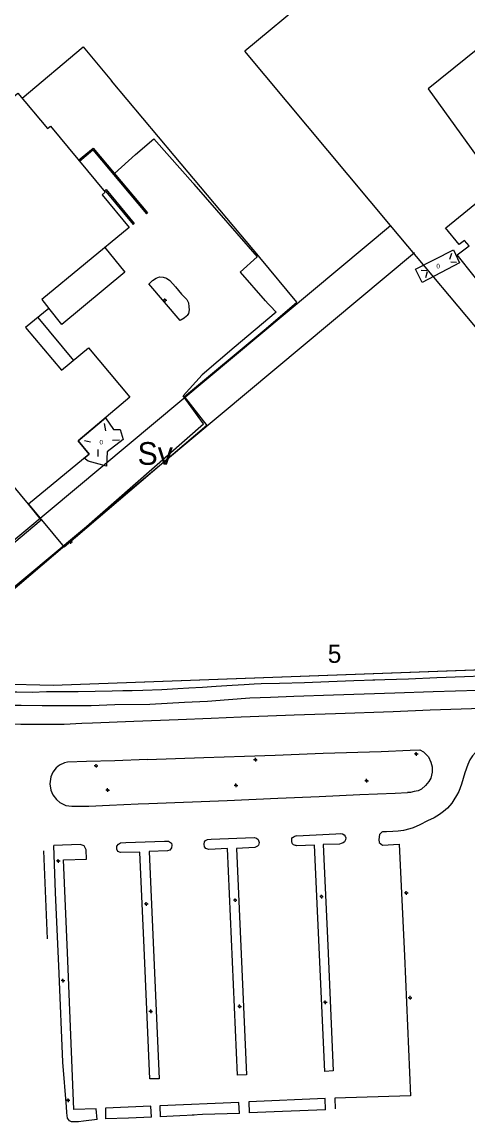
# Model space of a CAD drawing. Extents: x 1517229 to 1518128, y 6494851 to 6495271.
# Drawn here: x 1517777.6 to 1517875.8, y 6494851.1 to 6495093.3 of the extents above; entities that cross this region are included whole.
import ezdxf

# ---------------------------------------------------------------- set-up
doc = ezdxf.new("R2010")
doc.units = 0
doc.layers.add('Karta', color=7, linetype='Continuous')

msp = doc.modelspace()

# ---------------------------------------------------------------- linework, layer by layer
at = {"layer": 'Karta'}
for p, q in [((1517881.78, 6495132.98), (1517826.66, 6495086.92)), ((1517858.73, 6495048.55), (1517826.66, 6495086.92)), ((1517811.14, 6495063.95), (1517797.36, 6495080.37)), ((1517830.07, 6495041.4), (1517811.14, 6495063.95)), ((1517805.03, 6495051.11), (1517805.25, 6495051.3)), ((1517746.18, 6494954.49), (1517858.73, 6495048.55)), ((1517802.11, 6495048.74), (1517802.35, 6495048.94)), ((1517932.72, 6494960.01), (1517858.73, 6495048.55)), ((1517864, 6495042.53), (1517758.73, 6494954.55)), ((1517872.16, 6495042.37), (1517871.74, 6495041.05)), ((1517865.51, 6495038.71), (1517866.77, 6495038.65)), ((1517866.83, 6495038.29), (1517866.41, 6495036.97)), ((1517872.04, 6495040.51), (1517873.3, 6495040.45)), ((1517808.88, 6495032.09), (1517808.68, 6495032.09)), ((1517809.08, 6495032.29), (1517809.08, 6495032.49)), ((1517809.08, 6495031.89), (1517809.08, 6495031.69)), ((1517809.28, 6495032.09), (1517809.48, 6495032.09)), ((1517781.09, 6495028.24), (1517788.93, 6495018.83)), ((1517813.36, 6495010.85), (1517831.36, 6495025.87)), ((1517818.36, 6495004.5), (1517813.36, 6495010.85)), ((1517786.88, 6494977.74), (1517818.33, 6495004.54)), ((1517795.73, 6495004.9), (1517796.04, 6495003.32)), ((1517791.42, 6495001.18), (1517792.68, 6495000.9)), ((1517799.06, 6495001.29), (1517797.55, 6495001.22)), ((1517794.4, 6494997.68), (1517794.36, 6494999.18)), ((1517779.06, 6494987.16), (1517786.89, 6494977.73)), ((1517788.13, 6494978.85), (1517787.93, 6494978.85)), ((1517788.33, 6494979.05), (1517788.33, 6494979.25)), ((1517788.33, 6494978.65), (1517788.33, 6494978.45)), ((1517788.53, 6494978.85), (1517788.73, 6494978.85)), ((1517784.48, 6494947.28), (1517907.3, 6494951.79)), ((1517772.62, 6494947.63), (1517784.48, 6494947.28)), ((1517864.21, 6494932.17), (1517864.01, 6494932.17)), ((1517864.41, 6494932.37), (1517864.41, 6494932.57)), ((1517864.41, 6494931.97), (1517864.41, 6494931.77)), ((1517864.61, 6494932.17), (1517864.81, 6494932.17)), ((1517793.74, 6494929.55), (1517793.54, 6494929.55)), ((1517793.94, 6494929.75), (1517793.94, 6494929.95)), ((1517793.94, 6494929.35), (1517793.94, 6494929.15)), ((1517794.14, 6494929.55), (1517794.34, 6494929.55)), ((1517828.8, 6494930.9), (1517828.6, 6494930.9)), ((1517829, 6494931.1), (1517829, 6494931.3)), ((1517829, 6494930.7), (1517829, 6494930.5)), ((1517829.2, 6494930.9), (1517829.4, 6494930.9)), ((1517796.46, 6494924.42), (1517796.46, 6494924.62)), ((1517824.53, 6494925.25), (1517824.33, 6494925.25)), ((1517824.73, 6494925.45), (1517824.73, 6494925.65)), ((1517824.73, 6494925.05), (1517824.73, 6494924.85)), ((1517824.93, 6494925.25), (1517825.13, 6494925.25)), ((1517853.27, 6494926.27), (1517853.07, 6494926.27)), ((1517853.47, 6494926.47), (1517853.47, 6494926.67)), ((1517853.47, 6494926.07), (1517853.47, 6494925.87)), ((1517853.67, 6494926.27), (1517853.87, 6494926.27)), ((1517796.26, 6494924.22), (1517796.06, 6494924.22)), ((1517796.46, 6494924.02), (1517796.46, 6494923.82)), ((1517796.66, 6494924.22), (1517796.86, 6494924.22)), ((1517783.25, 6494891.47), (1517782.43, 6494910.86)), ((1517785.4, 6494908.6), (1517785.2, 6494908.6)), ((1517785.6, 6494908.8), (1517785.6, 6494909)), ((1517785.6, 6494908.4), (1517785.6, 6494908.2)), ((1517785.8, 6494908.6), (1517786, 6494908.6)), ((1517824.55, 6494900.17), (1517824.55, 6494900.37)), ((1517843.35, 6494900.77), (1517843.15, 6494900.77)), ((1517843.55, 6494900.97), (1517843.55, 6494901.17)), ((1517843.55, 6494900.57), (1517843.55, 6494900.37)), ((1517843.75, 6494900.77), (1517843.95, 6494900.77)), ((1517862.01, 6494901.57), (1517861.81, 6494901.57)), ((1517862.21, 6494901.77), (1517862.21, 6494901.97)), ((1517862.21, 6494901.37), (1517862.21, 6494901.17)), ((1517862.41, 6494901.57), (1517862.61, 6494901.57)), ((1517804.78, 6494899.15), (1517804.58, 6494899.15)), ((1517804.98, 6494899.35), (1517804.98, 6494899.55)), ((1517804.98, 6494898.95), (1517804.98, 6494898.75)), ((1517805.18, 6494899.15), (1517805.38, 6494899.15)), ((1517824.35, 6494899.97), (1517824.15, 6494899.97)), ((1517824.55, 6494899.77), (1517824.55, 6494899.57)), ((1517824.75, 6494899.97), (1517824.95, 6494899.97)), ((1517786.45, 6494882.25), (1517786.25, 6494882.25)), ((1517786.65, 6494882.45), (1517786.65, 6494882.65)), ((1517786.65, 6494882.05), (1517786.65, 6494881.85)), ((1517786.85, 6494882.25), (1517787.05, 6494882.25)), ((1517862.85, 6494878.48), (1517862.65, 6494878.48)), ((1517863.05, 6494878.68), (1517863.05, 6494878.88)), ((1517863.05, 6494878.28), (1517863.05, 6494878.08)), ((1517863.25, 6494878.48), (1517863.45, 6494878.48)), ((1517805.97, 6494875.68), (1517805.97, 6494875.88)), ((1517825.33, 6494876.57), (1517825.13, 6494876.57)), ((1517825.53, 6494876.77), (1517825.53, 6494876.97)), ((1517825.53, 6494876.37), (1517825.53, 6494876.17)), ((1517825.73, 6494876.57), (1517825.93, 6494876.57)), ((1517844.18, 6494877.48), (1517843.98, 6494877.48)), ((1517844.38, 6494877.68), (1517844.38, 6494877.88)), ((1517844.38, 6494877.28), (1517844.38, 6494877.08)), ((1517844.58, 6494877.48), (1517844.78, 6494877.48)), ((1517805.77, 6494875.48), (1517805.57, 6494875.48)), ((1517805.97, 6494875.28), (1517805.97, 6494875.08)), ((1517806.17, 6494875.48), (1517806.37, 6494875.48)), ((1517787.59, 6494855.91), (1517787.39, 6494855.91)), ((1517787.79, 6494856.11), (1517787.79, 6494856.31)), ((1517787.79, 6494855.71), (1517787.79, 6494855.51)), ((1517787.99, 6494855.91), (1517788.19, 6494855.91)), ((1517846.46, 6494856.36), (1517846.59, 6494853.99))]:
    msp.add_line(p, q, dxfattribs=at)
for points in [[(1517903.73, 6495083.96), (1517892.28, 6495099.05), (1517867.02, 6495078.59), (1517882.33, 6495057.34)], [(1517777.65, 6495076.56), (1517791.12, 6495087.86), (1517797.36, 6495080.37)], [(1517734.98, 6495043.01), (1517776.72, 6495077.67), (1517783.24, 6495069.88), (1517783.9, 6495070.37), (1517795.96, 6495055.9), (1517795.29, 6495055.3), (1517801.2, 6495048.09), (1517781.99, 6495032.2), (1517783.57, 6495030.27), (1517778.38, 6495026.04), (1517786.33, 6495016.68), (1517792.23, 6495021.58), (1517801.35, 6495010.73), (1517789.98, 6495001.11), (1517792.38, 6494998.21), (1517779.06, 6494987.16), (1517761.38, 6495008.42), (1517762.85, 6495009.67), (1517734.97, 6495043.01)], [(1517870.88, 6495048), (1517907.09, 6495077.52)], [(1517797.96, 6495060.01), (1517802.61, 6495064.18), (1517806.68, 6495067.6), (1517815.78, 6495057.24)], [(1517790.09, 6495062.95), (1517793.28, 6495065.59), (1517805.25, 6495051.3)], [(1517790.27, 6495062.73), (1517793.24, 6495065.19), (1517805.03, 6495051.11)], [(1517815.44, 6495057.63), (1517820.41, 6495051.88), (1517829.42, 6495041.61), (1517825.68, 6495038.23), (1517831.18, 6495031.94)], [(1517795.79, 6495056.15), (1517796.14, 6495056.46), (1517802.35, 6495048.94)], [(1517796, 6495055.92), (1517796.1, 6495056.01), (1517802.11, 6495048.74)], [(1517880.89, 6495032.64), (1517873.38, 6495042.06), (1517876.03, 6495044.05), (1517875.06, 6495045.24), (1517873.86, 6495044.31), (1517870.87, 6495048.01)], [(1517795.87, 6495043.68), (1517800.28, 6495038.27), (1517786.37, 6495026.75), (1517783.55, 6495030.3)], [(1517864.25, 6495038.89), (1517872.58, 6495043.15), (1517873.9, 6495040.33), (1517865.69, 6495036.01), (1517864.25, 6495038.89)], [(1517831.35, 6495025.87), (1517838.1, 6495031.66), (1517830, 6495041.47)], [(1517805.55, 6495035.62), (1517806.32, 6495036.4), (1517807.18, 6495036.94), (1517807.88, 6495037.19), (1517808.72, 6495037.18), (1517809.45, 6495036.94), (1517810.16, 6495036.4), (1517811.4, 6495035.03), (1517812.77, 6495033.38), (1517813.89, 6495032.22), (1517814.26, 6495031.47), (1517814.34, 6495030.64), (1517814.42, 6495029.98), (1517814.24, 6495029.18), (1517813.95, 6495028.68), (1517813.86, 6495028.6), (1517813.35, 6495028.15), (1517812.44, 6495027.62), (1517805.52, 6495035.66)], [(1517830.88, 6495032.29), (1517833.54, 6495029.45), (1517824.34, 6495021.63), (1517817.31, 6495015.66), (1517813.1, 6495011.01)], [(1517753.6, 6494949.92), (1517774.58, 6494967.4), (1517787.02, 6494978.07), (1517817.61, 6495004.85), (1517813.1, 6495011.01)], [(1517789.98, 6495001.11), (1517795.99, 6495006.19), (1517797.76, 6495003.64), (1517799.26, 6495003.64), (1517799.86, 6495001.39), (1517796.4, 6494998.68), (1517796.25, 6494995.52), (1517792.2, 6494996.64), (1517791.31, 6494997.32), (1517792.38, 6494998.21), (1517789.98, 6495001.11)], [(1517775.86, 6494978.65), (1517781.86, 6494983.74), (1517779.06, 6494987.16)], [(1517749.54, 6494952.96), (1517760.9, 6494949.53), (1517772.62, 6494947.63), (1517784.48, 6494947.28), (1517907.3, 6494951.79), (1517915.47, 6494952.77), (1517923.36, 6494955.07), (1517930.77, 6494958.64)], [(1517878.94, 6494949.26), (1517875.05, 6494949.12), (1517868.92, 6494948.91), (1517862.69, 6494948.66), (1517854.88, 6494948.42)], [(1517830.25, 6494947.57), (1517828.71, 6494947.5), (1517826.5, 6494947.4), (1517823.91, 6494947.22), (1517820.34, 6494947.01), (1517817.33, 6494946.77), (1517814.32, 6494946.66), (1517811.9, 6494946.49), (1517808.43, 6494946.31), (1517804.23, 6494946.14), (1517801.88, 6494946.07)], [(1517855.26, 6494948.38), (1517850.67, 6494948.27), (1517845.14, 6494948.03), (1517839.78, 6494947.85), (1517834.28, 6494947.71), (1517830.25, 6494947.57)], [(1517846.22, 6494945.16), (1517859.71, 6494945.61), (1517868.15, 6494945.93), (1517877.99, 6494946.21)], [(1517801.88, 6494946.07), (1517799.82, 6494946.03), (1517797.47, 6494945.96), (1517793.76, 6494945.89), (1517790.01, 6494945.82), (1517786.44, 6494945.85), (1517783.04, 6494945.82), (1517779.85, 6494945.71), (1517776.49, 6494945.78), (1517774.56, 6494945.78), (1517773.34, 6494945.89)], [(1517792.82, 6494942.85), (1517798.05, 6494943.02), (1517805.75, 6494943.16), (1517813.39, 6494943.54), (1517818.47, 6494943.82)], [(1517818.47, 6494943.82), (1517823.07, 6494944.14), (1517827.77, 6494944.49), (1517832.32, 6494944.67), (1517837.43, 6494944.88), (1517846.22, 6494945.16)], [(1517771.31, 6494938.96), (1517771.42, 6494940.68), (1517771.63, 6494942.08), (1517772.29, 6494942.61), (1517772.96, 6494942.92), (1517777.48, 6494942.92), (1517782.1, 6494942.82), (1517788.02, 6494942.82), (1517792.82, 6494942.85)], [(1517846.64, 6494941.09), (1517859.29, 6494941.55), (1517867.48, 6494941.86), (1517878.83, 6494942.25)], [(1517771.31, 6494938.96), (1517773.83, 6494938.79), (1517777.37, 6494938.69), (1517781.24, 6494938.72), (1517786.9, 6494938.72), (1517790.78, 6494938.93), (1517793.13, 6494939.04)], [(1517793.13, 6494939.04), (1517802.27, 6494939.42), (1517812.02, 6494939.76), (1517819.27, 6494940.07)], [(1517819.27, 6494940.07), (1517825.84, 6494940.35), (1517831.72, 6494940.57), (1517837.57, 6494940.78), (1517846.64, 6494941.09)], [(1517805.2, 6494930.94), (1517817.65, 6494931.37), (1517826.63, 6494931.68), (1517833.32, 6494931.93)], [(1517833.32, 6494931.93), (1517843.9, 6494932.31), (1517856.65, 6494932.74), (1517863.06, 6494932.98)], [(1517863.06, 6494932.98), (1517865.21, 6494933.08), (1517865.98, 6494932.63), (1517867.1, 6494931.51), (1517867.59, 6494930.39), (1517867.91, 6494929.33), (1517867.91, 6494928.14), (1517867.63, 6494926.85), (1517867.17, 6494926.11), (1517866.47, 6494925.2), (1517865.59, 6494924.43), (1517864.86, 6494924.08), (1517863.95, 6494923.87), (1517863.11, 6494923.69), (1517862.46, 6494923.66)], [(1517878.59, 6494933.21), (1517878.1, 6494932.86), (1517877.47, 6494932.47), (1517876.8, 6494931.74), (1517876.17, 6494930.86), (1517875.75, 6494929.81), (1517875.12, 6494928.02), (1517874.35, 6494925.54), (1517873.79, 6494923.92), (1517873.3, 6494923.01), (1517872.67, 6494922.07), (1517872.21, 6494921.33), (1517871.27, 6494920.24), (1517870.43, 6494919.51), (1517869.55, 6494918.84), (1517868.33, 6494918.07), (1517866.89, 6494917.41), (1517865.18, 6494916.57), (1517863.73, 6494915.92)], [(1517805.2, 6494930.94), (1517798.09, 6494930.66), (1517791.85, 6494930.49), (1517787.64, 6494930.39), (1517786.95, 6494930.24), (1517785.85, 6494929.7), (1517785.18, 6494929.13), (1517784.39, 6494928.17), (1517784.01, 6494927.12), (1517783.73, 6494925.58), (1517783.94, 6494924.18), (1517784.43, 6494923.16), (1517785.23, 6494922.15), (1517785.97, 6494921.45), (1517787.3, 6494920.82), (1517788.63, 6494920.64), (1517792.34, 6494920.68), (1517796.86, 6494920.89), (1517803.2, 6494921.17), (1517805.58, 6494921.27)], [(1517805.58, 6494921.27), (1517822.78, 6494921.94), (1517833.92, 6494922.4)], [(1517833.92, 6494922.4), (1517843.02, 6494922.82), (1517851.99, 6494923.24), (1517859.76, 6494923.53), (1517862.46, 6494923.66)], [(1517838.05, 6494914.17), (1517846.72, 6494914.6), (1517847.65, 6494914.65), (1517848.19, 6494914.59), (1517848.51, 6494914.37), (1517848.73, 6494914.06), (1517848.88, 6494913.71), (1517848.85, 6494913.28), (1517848.62, 6494912.83), (1517848.31, 6494912.58), (1517847.91, 6494912.42), (1517847.51, 6494912.31)], [(1517856.81, 6494914.96), (1517856.29, 6494914.46), (1517856.14, 6494913.3), (1517856.25, 6494912.66), (1517856.97, 6494912.07), (1517860.61, 6494912.28), (1517861.83, 6494887.68), (1517863.14, 6494856.91), (1517846.46, 6494856.36)], [(1517863.73, 6494915.92), (1517863.02, 6494915.65), (1517861.62, 6494915.34), (1517860.46, 6494915.13), (1517859.24, 6494915.09), (1517857.84, 6494915.02), (1517857, 6494914.99), (1517856.81, 6494914.96)], [(1517794.14, 6494851.67), (1517793.97, 6494854.02), (1517789.06, 6494853.86), (1517787.66, 6494888.48), (1517786.75, 6494908.85), (1517791.81, 6494909.03), (1517791.75, 6494911.09), (1517791.3, 6494911.94), (1517790.42, 6494912.26), (1517784.61, 6494911.98)], [(1517805.78, 6494860.61), (1517804.55, 6494889.5), (1517803.56, 6494910.57), (1517799.28, 6494910.45), (1517798.74, 6494910.67), (1517798.47, 6494911.21), (1517798.48, 6494911.87), (1517798.86, 6494912.3), (1517799.28, 6494912.58), (1517800.5, 6494912.68), (1517808.96, 6494912.98), (1517809.84, 6494912.95), (1517810.5, 6494912.51), (1517810.62, 6494912.07), (1517810.57, 6494911.48), (1517810.14, 6494911.01), (1517809.63, 6494910.82), (1517805.65, 6494910.71), (1517807.79, 6494860.64), (1517805.78, 6494860.61)], [(1517825.09, 6494861.47), (1517822.84, 6494911.34), (1517818.78, 6494911.13), (1517818.1, 6494911.38), (1517817.82, 6494911.69), (1517817.7, 6494912.28), (1517817.81, 6494912.82), (1517818.05, 6494913.12), (1517818.44, 6494913.33), (1517819.3, 6494913.37), (1517828.74, 6494913.78), (1517829.25, 6494913.66), (1517829.64, 6494913.31), (1517829.84, 6494912.7), (1517829.65, 6494912.07), (1517829.44, 6494911.87), (1517828.87, 6494911.6), (1517824.81, 6494911.37), (1517827.04, 6494861.53), (1517825.09, 6494861.47)], [(1517847.51, 6494912.31), (1517843.95, 6494912.23), (1517844.93, 6494890), (1517846.13, 6494862.4), (1517844.26, 6494862.27)], [(1517787.43, 6494854.45), (1517786.58, 6494864.33), (1517785.79, 6494883.81), (1517785, 6494901.63), (1517784.61, 6494911.98)], [(1517844.26, 6494862.27), (1517842.01, 6494912.07), (1517838.07, 6494911.97)], [(1517794.14, 6494851.67), (1517791.19, 6494851.28), (1517790.03, 6494851.15), (1517789.24, 6494851.13), (1517788.54, 6494851.18), (1517788.1, 6494851.38), (1517787.66, 6494851.99), (1517787.5, 6494853.13), (1517787.42, 6494854.57)], [(1517806.13, 6494852.17), (1517805.97, 6494854.61), (1517795.97, 6494854.2), (1517795.98, 6494851.79)], [(1517825.49, 6494853.03), (1517825.38, 6494855.41), (1517807.98, 6494854.66), (1517808.01, 6494852.3)], [(1517844.45, 6494853.83), (1517844.38, 6494856.32), (1517827.59, 6494855.58), (1517827.65, 6494853.11)], [(1517806.13, 6494852.17), (1517801.08, 6494851.95), (1517795.98, 6494851.79)], [(1517815.49, 6494852.63), (1517812.36, 6494852.45), (1517808.01, 6494852.3)], [(1517825.49, 6494853.03), (1517817.39, 6494852.76), (1517815.11, 6494852.6)], [(1517844.45, 6494853.83), (1517834.93, 6494853.46), (1517827.65, 6494853.11)]]:
    msp.add_lwpolyline(points, dxfattribs=at)
for centre in [(1517809.08, 6495032.09), (1517788.33, 6494978.85), (1517864.41, 6494932.17), (1517793.94, 6494929.55), (1517829, 6494930.9), (1517796.46, 6494924.22), (1517824.73, 6494925.25), (1517853.47, 6494926.27), (1517785.6, 6494908.6), (1517824.55, 6494899.97), (1517843.55, 6494900.77), (1517862.21, 6494901.57), (1517804.98, 6494899.15), (1517786.65, 6494882.25), (1517863.05, 6494878.48), (1517825.53, 6494876.57), (1517844.38, 6494877.48), (1517805.97, 6494875.48), (1517787.79, 6494855.91)]:
    msp.add_circle(centre, 0.2, dxfattribs=at)
msp.add_spline([(1517838.07, 6494911.97), (1517837.81, 6494912.01), (1517837.42, 6494912.14), (1517837.17, 6494912.41), (1517837.02, 6494912.72), (1517836.99, 6494913.22), (1517837.04, 6494913.57), (1517837.3, 6494913.88), (1517837.71, 6494914.09), (1517838.08, 6494914.18)], degree=3, dxfattribs=at)

# ---------------------------------------------------------------- texts
for p in [(1517868.84, 6495039.09), (1517794.69, 6495000.32)]:
    msp.add_text('0', height=1, dxfattribs=at).set_placement(p)
for s, height, p in [('Sv', 5, (1517803.05, 6494995.83)), ('5', 4, (1517844.94, 6494952.22))]:
    msp.add_text(s, height=height, rotation=0.0021, dxfattribs=at).set_placement(p)

doc.saveas('drawing.dxf')
